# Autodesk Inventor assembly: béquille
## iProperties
Shininess: 64.0
Length Units: 11269
Angle Units: 11279
Time Units: 11290
Mass Units: 11283
Length Display Precision: 3
Angle Display Precision: 2
Compacted: True
Created: 2006-01
Part Number: béquille
Document SubType Name: Assembly
Designer: riri
Density: 0.0
Volumn: 0.0
Area: 0.0
PropertySet Name: Model Information
Control State: 0
Master: False
Checked Out: False
Author: riri
